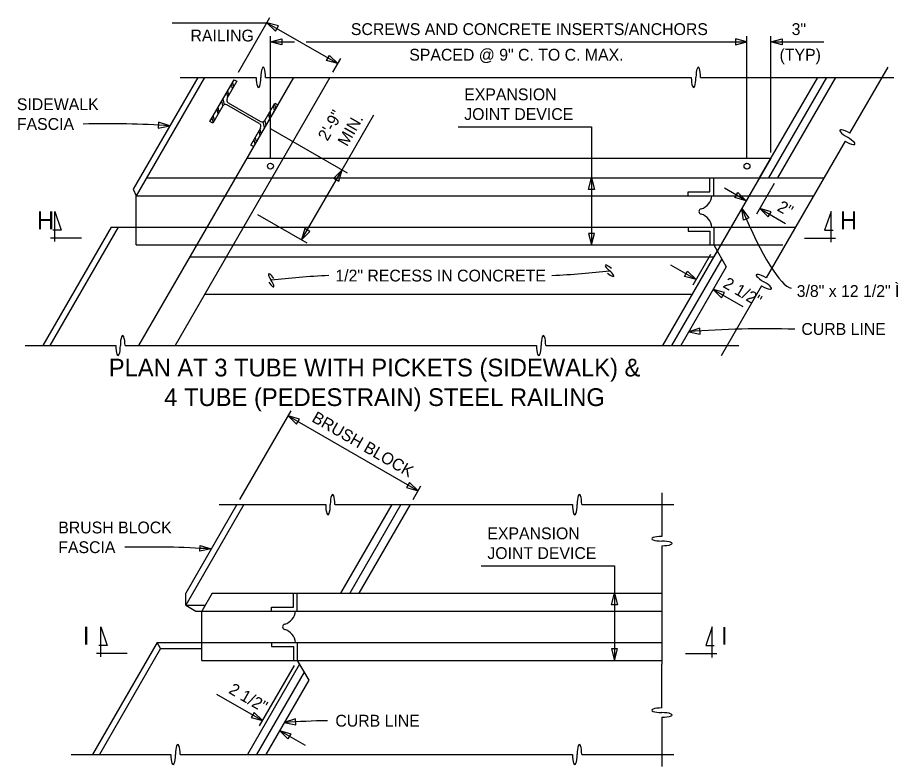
# Model space of a CAD drawing. Extents: x 19590 to 20151, y 19944 to 20103.
# Drawn here: x 19813.64 to 19848.36, y 20034.25 to 20063.78 of the extents above; entities that cross this region are included whole.
import ezdxf

# ---------------------------------------------------------------- set-up
doc = ezdxf.new("R2010")
doc.units = 0
for name, color, linetype in [('DETAIL_PR', 7, 'Continuous'), ('DETAIL_TEXT_DIMEN_PR', 7, 'Continuous'), ('Level 1', 7, 'Continuous'), ('MT_PAVT_MRKGS_EX', 7, 'Continuous'), ('MT_PAVT_MRKGS_EX_REF', 7, 'Continuous'), ('PAVT_MRKGS_QUANT', 7, 'Continuous')]:
    doc.layers.add(name, color=color, linetype=linetype)

# ---------------------------------------------------------------- blocks, each defined once
blk = doc.blocks.new('7')
at = {"layer": 'MT_PAVT_MRKGS_EX_REF'}
for p, q in [((-1.499, -0.188), (-1.5, 1.5)), ((-1.5, 1.5), (-1.136, 0.439)), ((0, 0), (-1.738, 0)), ((-1.136, 0.439), (-1.612, 0.439))]:
    blk.add_line(p, q, dxfattribs=at)
blk.add_text('H', height=1, dxfattribs=at).set_placement((-2.5, 0.5))
blk = doc.blocks.new('BRE')
at = {"layer": 'DETAIL_PR'}
for centre, ratio, start_param, end_param in [((0, 0.098), 0.230206, 4.712389, 7.853982), ((0, -0.098), 0.230204, 1.570796, 4.712389)]:
    blk.add_ellipse(centre, major_axis=(-0.427, 0), ratio=ratio, start_param=start_param, end_param=end_param, dxfattribs=at)
blk = doc.blocks.new('8')
at = {"layer": 'MT_PAVT_MRKGS_EX_REF'}
for p, q in [((1.5, 1.5), (1.135, 0.439)), ((1.499, -0.227), (1.5, 1.5)), ((0, 0), (1.752, 0)), ((1.135, 0.439), (1.612, 0.439))]:
    blk.add_line(p, q, dxfattribs=at)
blk.add_text('H', height=1, dxfattribs=at).set_placement((2, 0.5))
blk = doc.blocks.new('EJ3H')
at = {"layer": 'MT_PAVT_MRKGS_EX'}
for p, q in [((36.319, -34.278), (34.816, -36.882)), ((9.122, -34.682), (6.576, -39.091)), ((9.391, -34.682), (6.697, -39.348)), ((12.893, -34.682), (6.786, -45.257)), ((14.329, -34.682), (8.223, -45.257)), ((8.422, -34.682), (11.424, -34.682)), ((11.791, -34.682), (28.574, -34.682)), ((28.941, -34.682), (36.553, -34.682)), ((33.542, -34.682), (31.253, -38.648)), ((33.901, -34.682), (31.612, -38.648)), ((34.26, -34.682), (31.971, -38.648)), ((10.491, -35.133), (10.45, -34.947)), ((10.542, -35.044), (10.494, -34.871)), ((10.301, -35.462), (10.26, -35.277)), ((10.346, -35.385), (10.305, -35.2)), ((10.11, -35.793), (10.069, -35.608)), ((10.175, -35.757), (10.114, -35.531)), ((10.323, -35.68), (11.596, -36.415)), ((12.139, -35.731), (12.186, -35.905)), ((9.92, -36.122), (9.879, -35.937)), ((9.964, -36.045), (9.923, -35.861)), ((11.545, -36.504), (10.271, -35.769)), ((11.949, -36.062), (11.996, -36.237)), ((12.095, -35.808), (12.135, -35.993)), ((9.729, -36.453), (9.681, -36.279)), ((9.774, -36.376), (9.732, -36.19)), ((11.755, -36.654), (11.693, -36.427)), ((11.758, -36.392), (11.799, -36.576)), ((11.904, -36.139), (11.945, -36.324)), ((11.523, -36.799), (11.564, -36.984)), ((11.567, -36.722), (11.609, -36.908)), ((11.326, -37.139), (11.373, -37.314)), ((11.377, -37.051), (11.418, -37.237)), ((34.633, -37.2), (31.526, -42.581)), ((11.052, -37.87), (12.488, -37.87)), ((12.488, -37.87), (31.702, -37.87)), ((31.702, -37.87), (29.457, -41.758)), ((7.101, -38.648), (10.603, -38.648)), ((10.603, -38.648), (12.039, -38.648)), ((12.039, -38.648), (31.253, -38.648)), ((29.301, -39.192), (29.301, -38.648)), ((29.457, -39.347), (29.457, -38.648)), ((31.253, -38.648), (33.797, -38.648)), ((6.576, -39.091), (6.697, -39.348)), ((28.446, -39.347), (28.446, -39.192)), ((28.446, -39.192), (29.301, -39.192)), ((6.697, -39.348), (10.199, -39.348)), ((6.697, -41.291), (6.697, -39.348)), ((7.494, -39.348), (8.194, -39.348)), ((10.199, -39.348), (11.635, -39.348)), ((11.635, -39.348), (30.849, -39.348)), ((30.849, -39.348), (33.393, -39.348)), ((5.709, -40.592), (3.016, -45.257)), ((5.979, -40.592), (3.286, -45.257)), ((5.709, -40.592), (6.697, -40.592)), ((6.697, -40.592), (9.48, -40.592)), ((9.48, -40.592), (10.917, -40.592)), ((10.917, -40.592), (30.13, -40.592)), ((28.446, -40.591), (28.446, -40.747)), ((29.457, -40.591), (29.457, -41.291)), ((30.13, -40.592), (32.674, -40.592)), ((28.446, -40.747), (29.301, -40.747)), ((29.301, -40.747), (29.301, -41.291)), ((6.697, -41.291), (9.076, -41.291)), ((9.076, -41.291), (10.513, -41.291)), ((10.513, -41.291), (29.726, -41.291)), ((29.457, -41.291), (29.951, -42.147)), ((29.726, -41.291), (32.181, -41.291)), ((29.592, -41.525), (27.437, -45.257)), ((8.807, -41.758), (10.244, -41.758)), ((10.244, -41.758), (29.457, -41.758)), ((29.771, -41.836), (27.796, -45.257)), ((29.951, -42.147), (28.155, -45.257)), ((31.342, -42.899), (29.748, -45.661)), ((9.391, -43.235), (28.604, -43.235)), ((2.316, -45.257), (5.885, -45.257)), ((6.252, -45.257), (22.469, -45.257)), ((22.836, -45.257), (30.448, -45.257))]:
    blk.add_line(p, q, dxfattribs=at)
for points in [[(10.104, -35.804), (9.71, -36.485), (9.599, -36.422), (10.552, -34.771), (10.663, -34.835), (10.269, -35.517)], [(11.765, -36.381), (12.158, -35.699), (12.269, -35.762), (11.316, -37.412), (11.205, -37.349), (11.599, -36.667)]]:
    blk.add_lwpolyline(points, dxfattribs=at)
for centre in [(11.985, -38.181), (30.769, -38.181)]:
    blk.add_circle(centre, 0.117, dxfattribs=at)
for centre, radius, start, end in [((28.774, -39.282), 0.618, 288.1365, 353.9316), ((28.974, -39.969), 0.101, 94.4387, 265.5613), ((28.774, -40.657), 0.618, 6.0684, 71.8635)]:
    blk.add_arc(centre, radius, start, end, dxfattribs=at)
for centre, start_param, end_param in [((10.211, -35.864), 1.570796, 3.141593), ((10.375, -35.579), 3.141593, 4.712389), ((11.658, -36.319), 4.712389, 6.283185), ((11.494, -36.604), 0, 1.570796)]:
    blk.add_ellipse(centre, major_axis=(0.101, -0.058), ratio=0.993605, start_param=start_param, end_param=end_param, dxfattribs=at)
at = {"layer": 'MT_PAVT_MRKGS_EX_REF'}
for p, q in [((8.116, -32.525), (11.848, -32.525)), ((10.72, -34.48), (11.965, -32.323)), ((11.848, -32.525), (14.643, -34.139)), ((11.985, -37.87), (11.985, -33.05)), ((11.985, -33.283), (12.927, -33.283)), ((13.394, -33.283), (30.769, -33.283)), ((30.769, -37.87), (30.769, -33.05)), ((31.702, -37.637), (31.702, -33.05)), ((31.702, -33.283), (33.801, -33.283)), ((14.446, -34.48), (14.76, -33.937)), ((14.806, -38.327), (16.057, -36.161)), ((11.995, -36.704), (15.008, -38.444)), ((19.379, -36.626), (24.636, -36.626)), ((24.636, -36.626), (24.636, -41.291)), ((13.213, -41.088), (14.806, -38.327)), ((31.157, -40.058), (31.854, -38.85)), ((30.735, -39.544), (29.876, -39.049)), ((31.274, -39.856), (32.284, -40.439)), ((11.478, -40.086), (13.415, -41.204)), ((28.643, -42.857), (29.34, -41.649)), ((27.75, -42.072), (28.76, -42.655)), ((29.433, -43.044), (30.6, -43.717))]:
    blk.add_line(p, q, dxfattribs=at)
for centre, start, end in [((5.574, -76.003), 86.4465, 91.4029), ((31.478, -84.089), 88.2954, 94.3693)]:
    blk.add_arc(centre, 39.492, start, end, dxfattribs=at)
at = {"layer": 'PAVT_MRKGS_QUANT'}
for p, q in [((11.848, -32.525), (12.182, -32.852)), ((12.298, -32.651), (11.848, -32.525)), ((12.182, -32.852), (12.298, -32.651)), ((11.985, -33.283), (12.437, -33.166)), ((12.437, -33.399), (11.985, -33.283)), ((12.437, -33.166), (12.437, -33.399)), ((30.769, -33.283), (30.316, -33.166)), ((30.316, -33.166), (30.316, -33.399)), ((30.316, -33.399), (30.769, -33.283)), ((31.702, -33.283), (32.153, -33.166)), ((32.153, -33.399), (31.702, -33.283)), ((32.153, -33.166), (32.153, -33.399)), ((14.194, -34.014), (14.31, -33.812)), ((14.643, -34.139), (14.194, -34.014)), ((14.31, -33.812), (14.643, -34.139)), ((7.577, -36.446), (7.564, -36.679)), ((8.022, -36.587), (7.577, -36.446)), ((7.564, -36.679), (8.022, -36.587)), ((14.806, -38.327), (14.479, -38.661)), ((14.682, -38.778), (14.806, -38.327)), ((14.479, -38.661), (14.682, -38.778)), ((24.519, -39.099), (24.636, -38.648)), ((24.636, -38.648), (24.753, -39.099)), ((24.753, -39.099), (24.519, -39.099)), ((30.285, -39.42), (30.402, -39.218)), ((30.402, -39.218), (30.735, -39.544)), ((30.735, -39.544), (30.285, -39.42)), ((30.561, -39.846), (30.847, -40.215)), ((30.633, -40.307), (30.561, -39.846)), ((31.274, -39.856), (31.607, -40.183)), ((31.724, -39.981), (31.274, -39.856)), ((30.847, -40.215), (30.633, -40.307)), ((31.607, -40.183), (31.724, -39.981)), ((13.338, -40.637), (13.213, -41.088)), ((13.213, -41.088), (13.54, -40.754)), ((13.54, -40.754), (13.338, -40.637)), ((24.753, -40.84), (24.519, -40.84)), ((24.519, -40.84), (24.636, -41.291)), ((24.636, -41.291), (24.753, -40.84)), ((28.31, -42.53), (28.426, -42.328)), ((28.426, -42.328), (28.76, -42.655)), ((28.76, -42.655), (28.31, -42.53)), ((29.433, -43.044), (29.766, -43.371)), ((29.882, -43.168), (29.433, -43.044)), ((29.766, -43.371), (29.882, -43.168)), ((28.914, -44.571), (28.47, -44.712)), ((28.47, -44.712), (28.927, -44.803)), ((28.927, -44.803), (28.914, -44.571))]:
    blk.add_line(p, q, dxfattribs=at)
for centre, major_axis, start_param, end_param in [((30.595, -36.676), (2.026, -6.314), 5.183087, 6.19004), ((22.424, -41.397), (6.628, 0.225), 4.805942, 5.164147), ((14.944, -43.59), (-6.628, -0.225), 4.805942, 5.164147)]:
    blk.add_ellipse(centre, major_axis=major_axis, ratio=0.169331, start_param=start_param, end_param=end_param, dxfattribs=at)
for p, xscale, yscale, rotation in [((11.607, -34.682), 0.9330357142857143, 0.9330357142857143, 90), ((28.757, -34.682), 0.9330357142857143, 0.9330357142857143, 90), ((34.725, -37.041), 0.9330354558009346, 0.9330354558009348, 149.99937467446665), ((25.352, -42.309), 0.6220238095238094, 0.6220238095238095, 140.4584237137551), ((12.016, -42.685), 0.6220238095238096, 0.6220238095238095, 123.8234494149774), ((31.434, -42.74), 0.9330354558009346, 0.9330354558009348, 149.99937467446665), ((6.068, -45.257), 0.9330357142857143, 0.9330357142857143, 90), ((22.652, -45.257), 0.9330357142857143, 0.9330357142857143, 90)]:
    blk.add_blockref('BRE', p, dxfattribs=dict(at, xscale=xscale, yscale=yscale, rotation=rotation))
at = {"layer": 'PAVT_MRKGS_QUANT', "xscale": 0.699772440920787, "yscale": 0.699772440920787}
for name, p in [('7', (4.53, -41.019)), ('8', (33.033, -41.019))]:
    blk.add_blockref(name, p, dxfattribs=at)
at = {"layer": 'DETAIL_TEXT_DIMEN_PR'}
for s, p in [('PLAN AT 3 TUBE WITH PICKETS (SIDEWALK) & ', (5.611, -46.475)), ('4 TUBE (PEDESTRAIN) STEEL RAILING', (7.798, -47.642))]:
    blk.add_text(s, height=0.69987, dxfattribs=at).set_placement(p)
at = {"layer": 'MT_PAVT_MRKGS_EX_REF'}
for s, height, p in [('SCREWS AND CONCRETE INSERTS/ANCHORS', 0.46652, (15.155, -33.011)), ('3"', 0.4665, (32.528, -33.011)), ('RAILING', 0.4665, (8.833, -33.264)), ('SPACED @ 9" C. TO C. MAX.', 0.46652, (17.457, -34.021)), ('(TYP)', 0.4665, (32.053, -34.021)), ('EXPANSION ', 0.4665, (19.623, -35.584)), ('SIDEWALK', 0.4665, (1.989, -35.973)), ('JOINT DEVICE', 0.46652, (19.623, -36.361)), ('FASCIA', 0.4665, (1.989, -36.751)), ('1/2" RECESS IN CONCRETE', 0.46652, (14.544, -42.73)), ('3/8" x 12 1/2" Ì', 0.46652, (32.728, -43.339)), ('CURB LINE', 0.4665, (32.913, -44.837))]:
    blk.add_text(s, height=height, dxfattribs=at).set_placement(p)
for s, rotation, p in [('2\'-9"', 60, (14.231, -37.222)), ('MIN.', 60, (15.006, -37.436)), ('2"', 330, (31.921, -39.914)), ('2 1/2"', 330, (29.787, -42.937))]:
    blk.add_text(s, height=0.4665, rotation=rotation, dxfattribs=at).set_placement(p)

msp = doc.modelspace()

# ---------------------------------------------------------------- linework, layer by layer
at = {"layer": 'DETAIL_PR'}
for p, q in [((19839.039, 20045.043), (19839.039, 20043.322)), ((19822.288, 20044.577), (19820.268, 20041.078)), ((19822.557, 20044.577), (19820.268, 20040.612)), ((19821.588, 20044.577), (19825.785, 20044.577)), ((19826.152, 20044.577), (19835.512, 20044.577)), ((19828.393, 20044.577), (19826.373, 20041.078)), ((19828.752, 20044.577), (19826.732, 20041.078)), ((19829.111, 20044.577), (19827.091, 20041.078)), ((19835.879, 20044.577), (19839.506, 20044.577)), ((19839.039, 20042.955), (19839.039, 20038.279)), ((19820.268, 20040.612), (19820.268, 20041.078)), ((19821.309, 20041.078), (19820.905, 20040.378)), ((19821.309, 20041.078), (19839.039, 20041.078)), ((19824.511, 20040.534), (19824.511, 20041.078)), ((19824.667, 20040.378), (19824.667, 20041.078)), ((19820.268, 20040.612), (19821.04, 20040.612)), ((19820.268, 20040.612), (19820.672, 20040.378)), ((19823.656, 20040.378), (19823.656, 20040.534)), ((19823.656, 20040.534), (19824.511, 20040.534)), ((19820.672, 20040.378), (19820.905, 20040.378)), ((19820.905, 20040.378), (19839.039, 20040.378)), ((19820.905, 20038.434), (19820.905, 20040.378)), ((19819.145, 20039.134), (19816.596, 20034.719)), ((19819.145, 20039.134), (19820.905, 20039.134)), ((19819.28, 20038.901), (19819.145, 20039.134)), ((19820.905, 20039.134), (19839.039, 20039.134)), ((19823.656, 20039.134), (19823.656, 20038.979)), ((19824.667, 20039.134), (19824.667, 20038.434)), ((19819.28, 20038.901), (19816.866, 20034.719)), ((19819.28, 20038.901), (19820.905, 20038.901)), ((19823.656, 20038.979), (19824.511, 20038.979)), ((19824.511, 20038.979), (19824.511, 20038.434)), ((19820.905, 20038.434), (19839.039, 20038.434)), ((19824.667, 20038.434), (19825.116, 20037.657)), ((19824.757, 20038.279), (19822.701, 20034.719)), ((19839.039, 20036.558), (19839.039, 20038.279)), ((19824.936, 20037.968), (19823.06, 20034.719)), ((19825.116, 20037.657), (19823.42, 20034.719)), ((19839.039, 20036.191), (19839.039, 20034.253)), ((19815.752, 20034.719), (19819.68, 20034.719)), ((19820.047, 20034.719), (19835.512, 20034.719)), ((19835.879, 20034.719), (19839.506, 20034.719))]:
    msp.add_line(p, q, dxfattribs=at)
for centre, radius, start, end in [((19823.984, 20040.444), 0.618, 288.1365, 353.9316), ((19824.184, 20039.756), 0.101, 94.4387, 265.5613), ((19823.984, 20039.069), 0.618, 6.0684, 71.8635)]:
    msp.add_arc(centre, radius, start, end, dxfattribs=at)
for centre, major_axis, ratio, start_param, end_param in [((19826.06, 20044.577), (0, -0.398), 0.230204, 1.570796, 4.712389), ((19835.787, 20044.577), (0, -0.398), 0.230204, 1.570796, 4.712389), ((19825.877, 20044.577), (0, -0.398), 0.230206, 4.712389, 7.853982), ((19835.604, 20044.577), (0, -0.398), 0.230206, 4.712389, 7.853982), ((19839.039, 20043.23), (0.398, 0), 0.230204, 1.570796, 4.712389), ((19839.039, 20043.047), (0.398, 0), 0.230206, 4.712389, 7.853982), ((19839.039, 20036.466), (0.398, 0), 0.230204, 1.570796, 4.712389), ((19839.039, 20036.282), (0.398, 0), 0.230206, 4.712389, 7.853982), ((19819.955, 20034.719), (0, -0.398), 0.230204, 1.570796, 4.712389), ((19835.787, 20034.719), (0, -0.398), 0.230204, 1.570796, 4.712389), ((19819.772, 20034.719), (0, -0.398), 0.230206, 4.712389, 7.853982), ((19835.604, 20034.719), (0, -0.398), 0.230206, 4.712389, 7.853982)]:
    msp.add_ellipse(centre, major_axis=major_axis, ratio=ratio, start_param=start_param, end_param=end_param, dxfattribs=at)
at = {"layer": 'DETAIL_TEXT_DIMEN_PR'}
for p, q in [((19822.404, 20044.779), (19824.424, 20048.277)), ((19824.307, 20048.075), (19829.425, 20045.12)), ((19829.228, 20044.779), (19829.542, 20045.322)), ((19831.916, 20042.167), (19837.173, 20042.167)), ((19837.173, 20042.167), (19837.173, 20038.434)), ((19816.917, 20038.575), (19816.916, 20039.756)), ((19816.916, 20039.756), (19817.171, 20039.014)), ((19841.022, 20039.756), (19840.766, 20039.014)), ((19841.021, 20038.548), (19841.022, 20039.756)), ((19817.171, 20039.014), (19816.838, 20039.014)), ((19840.766, 20039.014), (19841.1, 20039.014)), ((19817.966, 20038.707), (19816.749, 20038.707)), ((19839.972, 20038.707), (19841.198, 20038.707)), ((19823.177, 20035.854), (19824.55, 20038.232)), ((19821.476, 20037.106), (19823.294, 20036.056)), ((19823.967, 20035.667), (19824.977, 20035.084))]:
    msp.add_line(p, q, dxfattribs=at)
for centre, start, end in [((19818.83, 20003.412), 86.4465, 91.4029), ((19826.598, 19996.569), 91.0778, 93.5535)]:
    msp.add_arc(centre, 39.492, start, end, dxfattribs=at)
at = {"layer": 'Level 1'}
for p, q in [((19824.307, 20048.075), (19824.641, 20047.748)), ((19824.757, 20047.95), (19824.307, 20048.075)), ((19824.641, 20047.748), (19824.757, 20047.95)), ((19829.092, 20045.447), (19828.976, 20045.245)), ((19829.425, 20045.12), (19829.092, 20045.447)), ((19828.976, 20045.245), (19829.425, 20045.12)), ((19820.82, 20042.736), (19820.833, 20042.969)), ((19820.833, 20042.969), (19821.278, 20042.828)), ((19821.278, 20042.828), (19820.82, 20042.736)), ((19837.056, 20040.627), (19837.173, 20041.078)), ((19837.173, 20041.078), (19837.29, 20040.627)), ((19837.29, 20040.627), (19837.056, 20040.627)), ((19837.289, 20038.886), (19837.056, 20038.886)), ((19837.056, 20038.886), (19837.173, 20038.434)), ((19837.173, 20038.434), (19837.289, 20038.886)), ((19822.961, 20036.383), (19822.844, 20036.181)), ((19823.294, 20036.056), (19822.961, 20036.383)), ((19822.844, 20036.181), (19823.294, 20036.056)), ((19824.596, 20036.126), (19824.151, 20035.985)), ((19824.151, 20035.985), (19824.608, 20035.893)), ((19824.608, 20035.893), (19824.596, 20036.126)), ((19823.967, 20035.667), (19824.417, 20035.542)), ((19824.3, 20035.34), (19823.967, 20035.667)), ((19824.417, 20035.542), (19824.3, 20035.34))]:
    msp.add_line(p, q, dxfattribs=at)

# ---------------------------------------------------------------- block references
msp.add_blockref('EJ3H', (19811.624, 20096.106), dxfattribs=at)

# ---------------------------------------------------------------- texts
at = {"layer": 'DETAIL_TEXT_DIMEN_PR'}
for s, height, p in [('BRUSH BLOCK', 0.46652, (19825.201, 20047.874)), ('2 1/2"', 0.4665, (19821.925, 20037.162))]:
    msp.add_text(s, height=height, rotation=330, dxfattribs=at).set_placement(p)
for s, height, p in [('BRUSH BLOCK', 0.46652, (19815.245, 20043.441)), ('EXPANSION ', 0.4665, (19832.159, 20043.209)), ('FASCIA', 0.4665, (19815.245, 20042.664)), ('JOINT DEVICE', 0.46652, (19832.159, 20042.431)), ('I', 0.7, (19816.216, 20039.057)), ('I', 0.7, (19841.371, 20039.056)), ('CURB LINE', 0.4665, (19826.167, 20035.821))]:
    msp.add_text(s, height=height, dxfattribs=at).set_placement(p)

doc.saveas('drawing.dxf')
